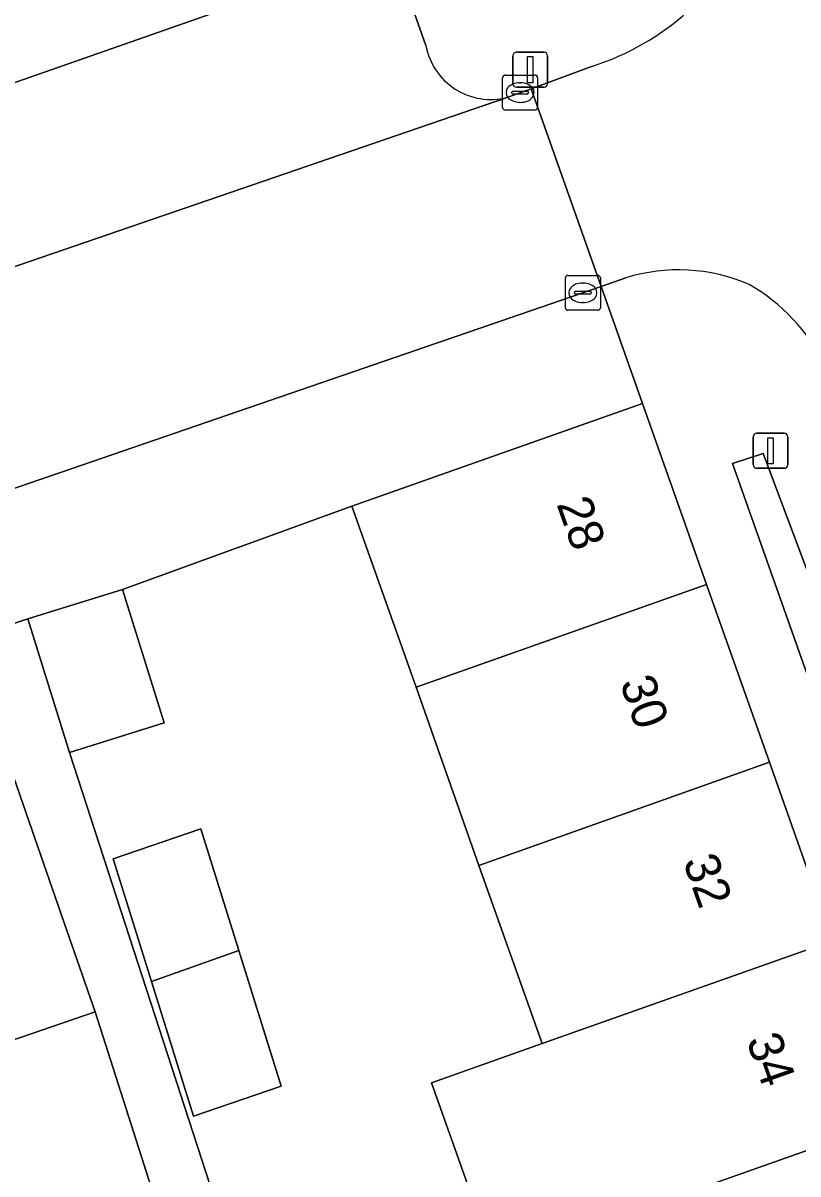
# Model space of a CAD drawing. Extents: x 159371 to 159986, y 382987 to 383597.
# Drawn here: x 159680.79 to 159702.95, y 383282.47 to 383315.4 of the extents above; entities that cross this region are included whole.
import ezdxf

# ---------------------------------------------------------------- set-up
doc = ezdxf.new("R2010")
doc.units = 0
for name, color, linetype in [('IMGEO_Erf', 7, 'Continuous'), ('IMGEO_Groenvoorziening', 7, 'Continuous'), ('IMGEO_Kolk', 7, 'Continuous'), ('IMGEO_Lichtmast', 7, 'Continuous'), ('IMGEO_Muur', 7, 'Continuous'), ('IMGEO_Pand', 7, 'Continuous'), ('IMGEO_Pand_nummerreeks', 7, 'Continuous'), ('IMGEO_Parkeervlak_open', 7, 'Continuous'), ('IMGEO_Rijbaan_lokaal_gesloten', 7, 'Continuous'), ('IMGEO_Rijbaan_lokaal_open', 7, 'Continuous'), ('IMGEO_Voetpad_open', 7, 'Continuous')]:
    doc.layers.add(name, color=color, linetype=linetype)

msp = doc.modelspace()

# ---------------------------------------------------------------- linework, layer by layer
at = {"layer": 'IMGEO_Erf'}
msp.add_lwpolyline([(159694.28, 383279.979), (159692.475, 383285.082), (159695.634, 383286.202), (159693.83, 383291.302), (159692.029, 383296.394), (159690.196, 383301.576), (159683.632, 383299.194), (159684.824, 383295.38), (159682.116, 383294.534), (159689.815, 383270.843)], dxfattribs=at)
for points in [[(159685.665, 383284.125), (159684.461, 383287.977), (159683.364, 383291.49), (159685.871, 383292.349), (159686.96, 383288.864), (159688.172, 383284.984)], [(159684.618, 383281.589), (159682.85, 383287.113), (159677.624, 383285.316), (159676.828, 383287.631), (159671.727, 383285.86), (159666.636, 383284.092), (159665.951, 383283.854), (159661.227, 383282.213), (159663.782, 383274.935), (159667.58, 383276.163), (159668.398, 383273.636), (159664.598, 383272.413), (159664.66, 383272.22), (159668.458, 383273.449), (159678.888, 383276.992), (159681.963, 383278.01), (159681.188, 383280.538)]]:
    msp.add_lwpolyline(points, close=True, dxfattribs=at)
at = {"layer": 'IMGEO_Groenvoorziening'}
msp.add_lwpolyline([(159701.08, 383302.797), (159703.6, 383295.685), (159704.607, 383296.025), (159701.962, 383303.085)], close=True, dxfattribs=at)
at = {"layer": 'IMGEO_Kolk'}
for p, q in [((159694.505, 383312.981), (159694.505, 383313.833)), ((159694.58, 383313.907), (159695.432, 383313.907)), ((159695.506, 383313.833), (159695.506, 383312.981)), ((159694.807, 383313.45), (159695.205, 383313.45)), ((159694.993, 383313.687), (159695.018, 383313.687)), ((159694.764, 383313.401), (159694.764, 383313.413)), ((159695.202, 383313.364), (159694.804, 383313.364)), ((159695.016, 383313.127), (159694.991, 383313.127)), ((159695.248, 383313.413), (159695.248, 383313.401)), ((159695.432, 383312.907), (159694.58, 383312.907)), ((159696.375, 383308.179), (159697.227, 383308.179)), ((159696.3, 383307.253), (159696.3, 383308.105)), ((159696.788, 383307.959), (159696.813, 383307.959)), ((159697.301, 383308.105), (159697.301, 383307.253)), ((159696.559, 383307.673), (159696.559, 383307.685)), ((159696.997, 383307.636), (159696.599, 383307.636)), ((159696.602, 383307.722), (159697, 383307.722)), ((159697.043, 383307.685), (159697.043, 383307.673)), ((159697.227, 383307.179), (159696.375, 383307.179)), ((159696.811, 383307.399), (159696.786, 383307.399))]:
    msp.add_line(p, q, dxfattribs=at)
for points in [[(159694.505, 383312.981), (159694.505, 383313.833)], [(159694.58, 383313.907), (159695.432, 383313.907)], [(159695.506, 383313.833), (159695.506, 383312.981)], [(159695.432, 383312.907), (159694.58, 383312.907)], [(159696.375, 383308.179), (159697.227, 383308.179)], [(159696.3, 383307.253), (159696.3, 383308.105)], [(159697.301, 383308.105), (159697.301, 383307.253)], [(159697.227, 383307.179), (159696.375, 383307.179)]]:
    msp.add_lwpolyline(points, dxfattribs=at)
for centre, radius, start, end in [((159694.582, 383313.831), 0.0765, 91.552, 178.448), ((159694.582, 383313.831), 0.0765, 91.552, 178.448), ((159695.43, 383313.831), 0.0765, 1.552, 88.448), ((159695.43, 383313.831), 0.0765, 1.552, 88.448), ((159694.804, 383313.41), 0.0403, 85.8775, 175.7526), ((159695.209, 383313.412), 0.0386, 1.7309, 96.639), ((159694.801, 383313.4), 0.0366, 178.938, 274.7102), ((159695.205, 383313.407), 0.043, 264.8664, 352.4533), ((159694.582, 383312.983), 0.0765, 181.552, 268.448), ((159694.582, 383312.983), 0.0765, 181.552, 268.448), ((159695.43, 383312.983), 0.0765, 271.552, 358.448), ((159695.43, 383312.983), 0.0765, 271.552, 358.448), ((159696.377, 383308.103), 0.0765, 91.552, 178.448), ((159696.377, 383308.103), 0.0765, 91.552, 178.448), ((159697.225, 383308.103), 0.0765, 1.552, 88.448), ((159697.225, 383308.103), 0.0765, 1.552, 88.448), ((159696.599, 383307.682), 0.0403, 85.8775, 175.7526), ((159696.596, 383307.672), 0.0366, 178.938, 274.7102), ((159697, 383307.679), 0.043, 264.8664, 352.4533), ((159697.004, 383307.684), 0.0386, 1.7309, 96.639), ((159696.377, 383307.255), 0.0765, 181.552, 268.448), ((159696.377, 383307.255), 0.0765, 181.552, 268.448), ((159697.225, 383307.255), 0.0765, 271.552, 358.448), ((159697.225, 383307.255), 0.0765, 271.552, 358.448)]:
    msp.add_arc(centre, radius, start, end, dxfattribs=at)
for centre, major_axis, ratio, start_param, end_param in [((159694.992, 383313.407), (-0.387, 0.002), 0.722429, 4.712389, 7.853982), ((159695.017, 383313.407), (-0.39, 0.002), 0.717154, 1.570796, 4.712389), ((159696.787, 383307.679), (-0.387, 0.002), 0.722429, 4.712389, 7.853982), ((159696.812, 383307.679), (-0.39, 0.002), 0.717154, 1.570796, 4.712389)]:
    msp.add_ellipse(centre, major_axis=major_axis, ratio=ratio, start_param=start_param, end_param=end_param, dxfattribs=at)
at = {"layer": 'IMGEO_Lichtmast'}
for p, q in [((159694.802, 383313.661), (159694.802, 383314.461)), ((159694.802, 383314.461), (159694.802, 383313.661)), ((159694.902, 383314.561), (159695.692, 383314.561)), ((159695.692, 383314.561), (159694.902, 383314.561)), ((159695.792, 383314.461), (159695.792, 383313.661)), ((159695.792, 383313.661), (159695.792, 383314.461)), ((159695.692, 383313.561), (159694.902, 383313.561)), ((159694.902, 383313.561), (159695.692, 383313.561)), ((159701.672, 383302.76), (159701.672, 383303.56)), ((159701.672, 383303.56), (159701.672, 383302.76)), ((159701.772, 383303.66), (159702.562, 383303.66)), ((159702.562, 383303.66), (159701.772, 383303.66)), ((159702.662, 383303.56), (159702.662, 383302.76)), ((159702.662, 383302.76), (159702.662, 383303.56)), ((159702.562, 383302.66), (159701.772, 383302.66)), ((159701.772, 383302.66), (159702.562, 383302.66))]:
    msp.add_line(p, q, dxfattribs=at)
for points in [[(159695.222, 383314.436), (159695.372, 383314.436), (159695.372, 383313.686), (159695.222, 383313.686), (159695.222, 383314.436)], [(159702.092, 383303.535), (159702.242, 383303.535), (159702.242, 383302.785), (159702.092, 383302.785), (159702.092, 383303.535)]]:
    msp.add_lwpolyline(points, dxfattribs=at)
for centre, start, end in [((159694.902, 383314.461), 90, 180), ((159694.902, 383314.461), 90, 180), ((159695.692, 383314.461), 0, 90), ((159695.692, 383314.461), 360, 90), ((159694.902, 383313.661), 180, 270), ((159694.902, 383313.661), 180, 270), ((159695.692, 383313.661), 270, 0), ((159695.692, 383313.661), 270, 0), ((159701.772, 383303.56), 90, 180), ((159701.772, 383303.56), 90, 180), ((159702.562, 383303.56), 0, 90), ((159702.562, 383303.56), 360, 90), ((159701.772, 383302.76), 180, 270), ((159701.772, 383302.76), 180, 270), ((159702.562, 383302.76), 270, 0), ((159702.562, 383302.76), 270, 0)]:
    msp.add_arc(centre, 0.1, start, end, dxfattribs=at)
at = {"layer": 'IMGEO_Muur'}
msp.add_lwpolyline([(159683.632, 383299.194), (159690.196, 383301.576)], dxfattribs=at)
at = {"layer": 'IMGEO_Pand'}
for points in [[(159700.334, 383299.34), (159698.504, 383304.515), (159690.196, 383301.576), (159692.029, 383296.394)], [(159693.83, 383291.302), (159702.135, 383294.249), (159700.334, 383299.34), (159692.029, 383296.394)], [(159683.632, 383299.194), (159680.924, 383298.349), (159682.116, 383294.534), (159684.824, 383295.38)], [(159680.79, 383293.042), (159679.15, 383297.765), (159673.964, 383295.964), (159676.828, 383287.631), (159677.624, 383285.316), (159682.85, 383287.113), (159682.041, 383289.441)], [(159695.634, 383286.202), (159703.94, 383289.147), (159702.135, 383294.249), (159693.83, 383291.302)], [(159684.461, 383287.977), (159686.96, 383288.864), (159685.871, 383292.349), (159683.364, 383291.49)], [(159703.94, 383289.147), (159695.634, 383286.202), (159692.475, 383285.082), (159694.28, 383279.979), (159697.439, 383281.1), (159705.744, 383284.046)], [(159686.96, 383288.864), (159684.461, 383287.977), (159685.665, 383284.125), (159688.172, 383284.984)], [(159707.559, 383278.917), (159705.744, 383284.046), (159697.439, 383281.1), (159699.251, 383275.978)]]:
    msp.add_lwpolyline(points, close=True, dxfattribs=at)
at = {"layer": 'IMGEO_Parkeervlak_open'}
for points in [[(159692.313, 383314.752), (159691.347, 383317.482), (159664.149, 383307.952), (159665.099, 383305.268)], [(159663.863, 383302.701), (159694.633, 383313.268)]]:
    msp.add_lwpolyline(points, dxfattribs=at)
msp.add_arc((159694.166, 383315.093), 1.884, 190.4411, 284.3484, dxfattribs=at)
at = {"layer": 'IMGEO_Rijbaan_lokaal_gesloten'}
msp.add_lwpolyline([(159697.078, 383314.164), (159695.321, 383313.515), (159697.322, 383307.856), (159698.031, 383308.107)], dxfattribs=at)
for centre, radius, start, end in [((159694.822, 383321.239), 7.426, 287.6881, 312.0646), ((159699.541, 383303.234), 5.102, 66.7451, 107.2123), ((159698.792, 383303.142), 5.52, 26.6053, 59.9682)]:
    msp.add_arc(centre, radius, start, end, dxfattribs=at)
at = {"layer": 'IMGEO_Rijbaan_lokaal_open'}
msp.add_lwpolyline([(159657.704, 383294.673), (159659.67, 383295.06), (159662.587, 383295.897), (159664.842, 383296.641), (159677.362, 383300.995), (159696.805, 383307.682), (159697.322, 383307.856), (159695.321, 383313.515), (159694.923, 383313.368), (159694.633, 383313.268), (159663.863, 383302.701), (159660.039, 383301.419), (159659.847, 383301.335), (159657.432, 383300.795)], close=True, dxfattribs=at)
at = {"layer": 'IMGEO_Voetpad_open'}
for points in [[(159664.149, 383307.952), (159691.347, 383317.482), (159692.313, 383314.752)], [(159694.633, 383313.268), (159694.923, 383313.368), (159695.321, 383313.515), (159697.078, 383314.164)], [(159668.862, 383294.193), (159673.964, 383295.964), (159679.15, 383297.765), (159680.924, 383298.349), (159683.632, 383299.194), (159690.196, 383301.576), (159698.504, 383304.515), (159697.322, 383307.856), (159696.805, 383307.682), (159677.362, 383300.995), (159664.842, 383296.641), (159662.587, 383295.897), (159659.67, 383295.06), (159657.704, 383294.673), (159654.709, 383294.462)], [(159698.031, 383308.107), (159697.322, 383307.856), (159698.504, 383304.515), (159700.334, 383299.34), (159702.135, 383294.249), (159703.94, 383289.147), (159705.744, 383284.046), (159707.559, 383278.917), (159709.366, 383273.807), (159711.174, 383268.697), (159712.978, 383263.595), (159714.782, 383258.494), (159716.587, 383253.394), (159717.787, 383250), (159718.404, 383248.254), (159720.212, 383243.144), (159721.927, 383238.295)], [(159702.568, 383230.227), (159698.877, 383242.072), (159697.469, 383246.61), (159696.512, 383249.693), (159695.59, 383252.391), (159695.365, 383253.117), (159694.182, 383256.929), (159693.225, 383260.012), (159692.11, 383263.497), (159690.932, 383267.268), (159689.815, 383270.843), (159682.116, 383294.534), (159680.924, 383298.349), (159679.15, 383297.765), (159680.79, 383293.042), (159682.041, 383289.441), (159682.85, 383287.113), (159684.618, 383281.589), (159685.392, 383279.061), (159681.963, 383278.01), (159678.888, 383276.992)]]:
    msp.add_lwpolyline(points, dxfattribs=at)
msp.add_lwpolyline([(159703.6, 383295.685), (159701.08, 383302.797), (159701.962, 383303.085), (159704.607, 383296.025)], close=True, dxfattribs=at)
for centre, radius, start, end in [((159694.822, 383321.239), 7.426, 287.6881, 312.0646), ((159694.166, 383315.093), 1.884, 190.4411, 284.3484), ((159699.541, 383303.234), 5.102, 66.7451, 107.2123), ((159698.792, 383303.142), 5.52, 26.6053, 59.9682)]:
    msp.add_arc(centre, radius, start, end, dxfattribs=at)

# ---------------------------------------------------------------- texts
at = {"layer": 'IMGEO_Pand_nummerreeks'}
for s, rotation, p in [('28', 289.4796, (159696.041, 383301.64)), ('30', 289.4796, (159697.85, 383296.526)), ('32', 289.4796, (159699.657, 383291.417)), ('34', 289.4804, (159701.468, 383286.3))]:
    msp.add_text(s, height=1, rotation=rotation, dxfattribs=at).set_placement(p)

doc.saveas('drawing.dxf')
